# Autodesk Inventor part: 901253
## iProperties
Created: 2007-10
Part Number: 901253
Document SubType Name: Modeling
Designer: TH
Density: 1.13 g/cm^3
Mass: 11.4749 g
Surface Area: 58.4644 cm^2
Volume: 10.1548 cm^3
Material: Nylon Composite (Nylon, molybdenum disulphide)
Description: MOTOR SIDE MOUNT COVER
Component Category: Electrical
Author: TH
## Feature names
1. TaggingFeature2
